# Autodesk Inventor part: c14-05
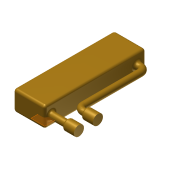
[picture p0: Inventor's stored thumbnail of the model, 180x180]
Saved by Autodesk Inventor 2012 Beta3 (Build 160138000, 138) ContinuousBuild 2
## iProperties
Created: 2011-01
Part Number: c14-05
Material: Default
Document SubType Name: Modeling
Designer: Beta-8540w
Density: 1 g/cm^3
Author: Beta-8540w
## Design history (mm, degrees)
sketch "Sketch1"
  geometry: L1 (25, -80)-(-25, -80); L2 (-25, -80)-(-25, 80); L3 (-25, 80)-(25, 80); L4 (25, 80)-(25, -80); 3 further points
  constraints: 8 end point, 2 midpoint, 2 parallel, 1 horizontal, 1 horizontal alignment, 1 perpendicular, 1 vertical alignment
  dimensions: "d0" = 50 distance of L2.end L3.end; "d1" = 160 distance of L1.end L2.end
extrude "Extrusion1" new body sketch "Sketch1" distance "d2" = 32; taper "d3" = 0 deg
workplane "Work Plane1"
sketch "Sketch2"
  geometry: L1 (0, 0)-(-32, 0) reference; C1 r 5 at (-16, 10); 2 further points
  constraints: 1 centre point, 1 midpoint, 1 vertical alignment
  dimensions: "d4" = 10 diameter of C1; "d5" = 10 distance from line of C1.centre L1
extrude "Extrusion2" join sketch "Sketch2" distance "d6" = 26; taper "d7" = 0 deg
sketch "Sketch3"
  geometry: L1 (0, 160)-(-32, 160) reference; C1 r 5 at (-16, 146); 2 further points
  constraints: 1 centre point, 1 midpoint, 1 vertical alignment
  dimensions: "d8" = 10 diameter of C1; "d9" = 14 distance from line of L1 C1.centre
sketch "Sketch4"
  geometry: L1 (0, 146)-(5, 146); L2 (13, 138)-(13, 48); L3 (21, 40)-(26, 40); A1 r 8 centre (5, 138) between (13, 138) and (5, 146); A2 r 8 centre (21, 48) between (13, 48) and (21, 40); 1 further point
  constraints: 6 end point, 4 point on circle, 4 tangent, 2 centre point, 1 equal radius, 1 horizontal, 1 parallel, 1 perpendicular
  dimensions: "d10" = 8 radius of A2; "d11" = 5 distance of L1.start L1.end; "d12" = 106 distance between parallel lines of L1 L3; "d13" = 5 distance of L3.start L3.end
sweep "Sweep1" sketch "Sketch3", "Sketch4" dims "d14" = 0
sketch "Sketch5"
  geometry: C1 r 5 at (0, 0) reference; C2 r 5 at (0, 30) reference; C3 r 8 at (0, 0); C4 r 8 at (0, 30); 1 further point
  constraints: 2 centre point, 2 coincident, 1 equal radius
  dimensions: "d16" = 16 diameter of C3
extrude "Extrusion3" join sketch "Sketch5" distance "d17" = 18; taper "d18" = 0 deg
fillet "Fillet1" dims "d15" = 4, "d19" = 2
body "Solid1"
node "Projected Loop1"
